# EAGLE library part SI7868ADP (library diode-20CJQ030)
Vishay Siliconix Si7868ADP N-Channel 20-V (D-S) MOSFET FEATURES TrenchFET Power MOSFET Low rDS(on) PWM (Qgd and Rg) Optimized 100% Rg Tested RoHS Compliant APPLICATIONS Low Output Voltage Synchronous Rectifier Please send any comments to: messi@users.sourceforge.net
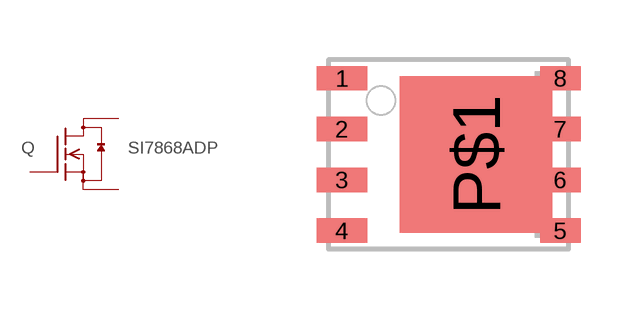
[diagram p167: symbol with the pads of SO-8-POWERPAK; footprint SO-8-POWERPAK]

Designator prefix Q

## SI7868ADP  [SO-8-POWERPAK]
1  S  pas
2  S  pas
3  S  pas
4  G  pas
5  D  pas
6  D  pas
7  D  pas
8  D  pas

## Footprint SO-8-POWERPAK (pad centres in mm)
Vishay's PowerPAK SO-8 Single for MOS-FETs
smd 1.27 x 0.61: 1 -2.667,2.54; 2 -2.667,1.27; 3 -2.667,0; 4 -2.667,-1.27
smd 1.016 x 0.61: 5 2.794,-1.27; 6 2.794,0; 7 2.794,1.27; 8 2.794,2.54
smd 3.81 x 3.912: P$1 0.686,0.635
